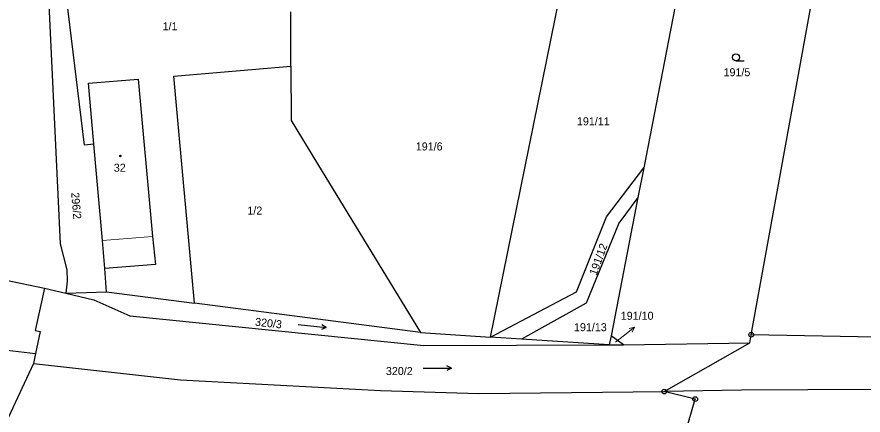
# Model space of a CAD drawing. Extents: x -769392 to -767038, y -1018329 to -1015269.
# Drawn here: x -768447.4 to -768267.7, y -1016436.2 to -1016351.8 of the extents above; entities that cross this region are included whole.
import ezdxf
from ezdxf.enums import TextEntityAlignment as Align

# ---------------------------------------------------------------- set-up
doc = ezdxf.new("R2010")
doc.units = 0
doc.header["$LTSCALE"] = 0.68
for name, color, linetype, lineweight in [('1', 7, 'Continuous', 25), ('3', 7, 'Continuous', 25), ('4', 7, 'Continuous', 13), ('5', 7, 'Continuous', 25), ('7', 7, 'Continuous', 13), ('8', 7, 'Continuous', 25)]:
    doc.layers.add(name, color=color, linetype=linetype, lineweight=lineweight)
doc.layers.add('2', color=7, linetype='Continuous')

msp = doc.modelspace()

# ---------------------------------------------------------------- linework, layer by layer
at = {"layer": '1'}
for p, q in [((-768441.14, -1016337.77), (-768438.23, -1016399.9)), ((-768433.06, -1016378.94), (-768437.56, -1016341.98)), ((-768306.44, -1016343.34), (-768314.31, -1016383.77)), ((-768291.49, -1016419.17), (-768277.72, -1016343.38)), ((-768346.82, -1016419.68), (-768332.13, -1016347.3)), ((-768389.23, -1016362.23), (-768389.26, -1016350.71)), ((-768414.08, -1016364.3), (-768389.23, -1016362.23)), ((-768389.23, -1016362.23), (-768389.2, -1016373.69)), ((-768409.73, -1016412.48), (-768414.08, -1016364.3)), ((-768432.22, -1016365.81), (-768421.65, -1016364.93)), ((-768431.07, -1016378.76), (-768432.22, -1016365.81)), ((-768421.65, -1016364.93), (-768418.64, -1016398.31)), ((-768389.2, -1016373.69), (-768383.56, -1016382.94)), ((-768431.07, -1016378.76), (-768433.06, -1016378.94)), ((-768429.26, -1016399.17), (-768431.07, -1016378.76)), ((-768383.56, -1016382.94), (-768361.69, -1016418.7)), ((-768322.25, -1016394.15), (-768314.31, -1016383.77)), ((-768314.31, -1016383.77), (-768315.54, -1016390.08)), ((-768315.54, -1016390.08), (-768321.25, -1016419.37)), ((-768315.54, -1016390.08), (-768319.61, -1016395.52)), ((-768328.61, -1016410.05), (-768322.25, -1016394.15)), ((-768319.61, -1016395.52), (-768326.54, -1016412.44)), ((-768418.64, -1016398.31), (-768418.01, -1016404.28)), ((-768438.23, -1016399.9), (-768436.84, -1016405.42)), ((-768428.77, -1016405.09), (-768429.26, -1016399.17)), ((-768436.84, -1016405.42), (-768436.72, -1016407.8)), ((-768418.01, -1016404.28), (-768428.77, -1016405.09)), ((-768428.36, -1016410.07), (-768428.77, -1016405.09)), ((-768449.69, -1016407.59), (-768441.56, -1016409.26)), ((-768436.72, -1016407.8), (-768437.03, -1016410.33)), ((-768441.56, -1016409.26), (-768437.03, -1016410.33)), ((-768437.03, -1016410.33), (-768428.36, -1016410.07)), ((-768437.03, -1016410.33), (-768431.06, -1016411.75)), ((-768428.36, -1016410.07), (-768409.73, -1016412.48)), ((-768346.82, -1016419.68), (-768328.61, -1016410.05)), ((-768431.06, -1016411.75), (-768423.43, -1016415.13)), ((-768361.69, -1016418.7), (-768409.73, -1016412.48)), ((-768326.54, -1016412.44), (-768340.3, -1016420.11)), ((-768423.43, -1016415.13), (-768361.02, -1016421.46)), ((-768361.69, -1016418.7), (-768346.82, -1016419.68)), ((-768340.3, -1016420.11), (-768346.82, -1016419.68)), ((-768321.63, -1016421.33), (-768340.3, -1016420.11)), ((-768321.25, -1016419.37), (-768321.63, -1016421.33)), ((-768318.63, -1016421.28), (-768321.25, -1016419.37)), ((-768291.8, -1016420.87), (-768291.49, -1016419.17)), ((-768361.02, -1016421.46), (-768321.63, -1016421.33)), ((-768321.63, -1016421.33), (-768318.63, -1016421.28)), ((-768318.63, -1016421.28), (-768291.8, -1016420.87)), ((-768309.95, -1016431.2), (-768291.8, -1016420.87)), ((-768443.48, -1016423.15), (-768443.93, -1016425.28)), ((-768443.93, -1016425.28), (-768412.66, -1016428.75)), ((-768412.66, -1016428.75), (-768370.21, -1016430.96)), ((-768370.21, -1016430.96), (-768349.31, -1016431.64)), ((-768349.31, -1016431.64), (-768309.95, -1016431.2))]:
    msp.add_line(p, q, dxfattribs=at)
for points in [[(-768441.56, -1016409.26), (-768443.51, -1016418.28), (-768442.5, -1016418.45), (-768443.48, -1016423.15)], [(-768149.56, -1016435.17), (-768165.81, -1016430.63), (-768189.18, -1016424.81), (-768200.67, -1016422.65), (-768213.51, -1016421.11), (-768221.38, -1016420.5), (-768227.18, -1016420.37), (-768291.49, -1016419.17)], [(-768456.72, -1016425.79), (-768452.42, -1016422.86), (-768450.67, -1016422.31), (-768443.48, -1016423.15)], [(-768443.93, -1016425.28), (-768449.29, -1016436.8), (-768497.79, -1016498.96)], [(-768038.72, -1016499.94), (-768042.29, -1016496.26), (-768055.76, -1016484.64), (-768082.41, -1016467.78), (-768121.86, -1016453.69), (-768206.72, -1016432.48), (-768223, -1016430.55), (-768293.54, -1016430.88), (-768309.95, -1016431.2)], [(-768305.44, -1016439.92), (-768303.39, -1016432.81), (-768309.95, -1016431.2)]]:
    msp.add_lwpolyline(points, dxfattribs=at)
at = {"layer": '3'}
for p, q in [((-768294.723, -1016361.08), (-768292.973, -1016361.08)), ((-768381.72, -1016417.634), (-768382.744, -1016418.03)), ((-768355.133, -1016426.269), (-768356.11, -1016426.77))]:
    msp.add_line(p, q, dxfattribs=at)
for points in [[(-768387.687, -1016417.007), (-768381.72, -1016417.634), (-768382.64, -1016417.033)], [(-768361.133, -1016426.269), (-768355.133, -1016426.269), (-768356.11, -1016425.767)]]:
    msp.add_lwpolyline(points, dxfattribs=at)
msp.add_circle((-768294.7229, -1016360.3298), 0.75, dxfattribs=at)
at = {"layer": '4'}
msp.add_line((-768429.26, -1016399.17), (-768418.64, -1016398.31), dxfattribs=at)
at = {"layer": '5'}
msp.add_circle((-768425.4468, -1016381.2492), 0.175, dxfattribs=at)
at = {"layer": '7'}
msp.add_line((-768316.285, -1016417.582), (-768317.383, -1016417.804), dxfattribs=at)
msp.add_lwpolyline([(-768320.29, -1016420.71), (-768318.65, -1016419.43), (-768316.285, -1016417.582), (-768316.766, -1016418.594)], dxfattribs=at)
at = {"layer": '8'}
for centre, radius in [((-768291.49, -1016419.1699), 0.5), ((-768291.49, -1016419.1699), 0.0303), ((-768309.95, -1016431.1999), 0.5), ((-768309.95, -1016431.1999), 0.0303), ((-768303.39, -1016432.8099), 0.5), ((-768303.39, -1016432.8099), 0.0303)]:
    msp.add_circle(centre, radius, dxfattribs=at)

# ---------------------------------------------------------------- texts
at = {"layer": '2'}
for s, p in [('1/1', (-768414.91, -1016354.605)), ('191/5', (-768294.52, -1016364.335)), ('191/11', (-768325.02, -1016374.745)), ('191/6', (-768359.87, -1016380.075)), ('32', (-768425.579, -1016384.585)), ('1/2', (-768396.9, -1016393.675)), ('191/13', (-768325.65, -1016418.405)), ('320/2', (-768366.21, -1016427.705))]:
    msp.add_text(s, height=1.7, dxfattribs=at).set_placement(p, align=Align.CENTER)
for s, rotation, p in [('296/2', 275, (-768435.6595, -1016391.8739)), ('191/12', 70, (-768323.1566, -1016403.4467)), ('320/3', 354, (-768394.0783, -1016417.5372))]:
    msp.add_text(s, height=1.7, rotation=rotation, dxfattribs=at).set_placement(p, align=Align.CENTER)
msp.add_text('191/10', height=1.7, dxfattribs=at).set_placement((-768319.19, -1016415.985))

doc.saveas('drawing.dxf')
